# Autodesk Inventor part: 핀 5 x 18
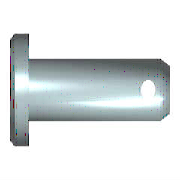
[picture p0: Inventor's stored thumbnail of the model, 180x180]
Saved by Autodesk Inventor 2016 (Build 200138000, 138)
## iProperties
Created: 2012-02
Part Number: 핀 5 x 18
Material: 강철
Description: 머리가 있는 클레비스 핀
Document SubType Name: Modeling
Standard: ISO 2341
Designer: test
Standard Revision: Second edition 1986-11-01
Standards Organization: ISO
Language: ko-KR
Size Designation: B - 5 x 18
Categories: <MemberInstance><Categories><Category DisplayName="조임쇠" InternalName="e4da775c-781d-43d5-af7c-5136215cf5a6" Mnemonic="FSTN"><Category DisplayName="핀" InternalNa
Density: 7.85 g/cm^3
Appearance: 강철
IsCustomPart: 1
Author: test
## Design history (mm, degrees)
sketch "스케치1"
  geometry: L1 (-1.6, 0)-(-1.6, 4); L2 (-1.6, 4)-(0, 4); L3 (0, 4)-(0, 2.5); L4 (0, 2.5)-(18, 2.5); L5 (18, 2.5)-(18, 0); L6 (-1.6, 0)-(18, 0); L7 (-4, 0)-(17, 0) reference; L8 (0, -0.98)-(0, 3.08) reference; C1 r 0.6 at (15.1, 0)
  constraints: 12 end point, 3 parallel, 2 collinear, 2 perpendicular, 1 centre point, 1 point on line, 1 vertical
  dimensions: "d0" = 5 diameter of L4 L6 (= NND); "d1" = 8 diameter of L2 L6 (= KOD); "d2" = 1.6 distance of L1.end L2.end (= KOH); "d3" = 18 distance of L3.end L4.end (= NLG); "d5" = 2.9 distance from line of L5 C1.centre (= DIST); "d6" = 1.2 diameter of C1 (= BOR)
revolve "본체" stored, may be unused: angle "d4" = 90 deg
extrude "구멍" cut sketch "스케치1" stored distance "d7" = 5 (= NND); taper "d8" = 0 deg
workaxis "Work Axis1"
workplane "Work Plane1"
body "Solid1"
chamfer "모따기1" distance "d9" = 1 (= PHH2); stored, may be unused: angle "d10" = 45 deg (= FAWI2), second distance "d16" = 1 (= PHH2)
chamfer "모따기2" distance "d11" = 2 (= PHH1); stored, may be unused: angle "d12" = 30 deg (= FAWI1), second distance "d17" = 2 (= PHH1)
other parameters: "PHH1" = 2 [user parameter; used in 2 equation terms], "PHH2" = 1 [user parameter; used in 2 equation terms], "KOD" = 8 [user parameter; used in 1 equation term], "KOH" = 1.6 [user parameter; used in 1 equation term], "NND" = 5 [user parameter; used in 2 equation terms], "FAWI1" = 30 deg [user parameter; used in 1 equation term], "FAWI2" = 45 deg [user parameter; used in 1 equation term], "DIST" = 2.9 [user parameter; used in 1 equation term], "BOR" = 1.2 [user parameter; used in 1 equation term], "NLG" = 18 [user parameter; used in 1 equation term], "d13" = 0, "d14" = 0, "d27" = 0, "d28" = 0, "d29" = 0, "d30" = 0, "d31" = 0
